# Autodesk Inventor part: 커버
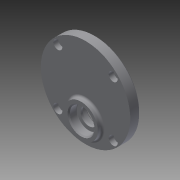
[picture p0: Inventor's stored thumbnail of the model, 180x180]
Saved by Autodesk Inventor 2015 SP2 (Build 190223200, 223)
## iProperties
Created: 2015-06
Part Number: 커버
Material: 일반
Document SubType Name: Modeling
Designer: AMC
Density: 1 g/cm^3
Appearance: 기본값
Author: AMC
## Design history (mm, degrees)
sketch "스케치1"
  geometry: C1 r 40 at (0, 0); 1 further point
  constraints: 1 centre point, 1 coincident
  dimensions: "d0" = 80 diameter of C1
extrude "돌출1" new body sketch "스케치1" distance "d1" = 9; taper "d2" = 0 deg
sketch "스케치2"
  geometry: C1 r 15 at (0, -20); 1 further point
  constraints: 1 centre point, 1 vertical alignment
  dimensions: "d3" = 30 diameter of C1; "d4" = 20 distance of point (0, 0) C1.centre
extrude "돌출2" join sketch "스케치2" distance "d5" = 4; taper "d6" = 0 deg
sketch "스케치3"
  geometry: C1 r 14 at (0, 20); C2 r 14 at (0, -11); 1 further point
  constraints: 2 centre point, 2 vertical alignment
  dimensions: "d7" = 28 diameter of C1; "d8" = 28 diameter of C2; "d9" = 11 distance of C2.centre point (0, 0); "d10" = 20 distance of point (0, 0) C1.centre
extrude "돌출3" join sketch "스케치3" distance "d11" = 3; taper "d12" = 0 deg
sketch "스케치4"
  geometry: C1 r 14 at (0, 0) reference; C2 r 14 at (0, -31) reference; C3 r 11 at (0, 0); 1 further point
  constraints: 1 centre point, 1 coincident
  dimensions: "d14" = 22 diameter of C3
extrude "돌출4" cut sketch "스케치4" distance "d15" = 7; taper "d16" = 0 deg
sketch "스케치5"
  geometry: C1 r 11 at (0, 0) reference; C2 r 40 at (0, -20) reference; C3 r 7.5 at (0, 0); 1 further point
  constraints: 1 centre point, 1 coincident
  dimensions: "d17" = 15 diameter of C3
extrude "돌출5" cut sketch "스케치5" distance "d18" = 2; taper "d19" = 0 deg
sketch "스케치6"
  geometry: C1 r 15 at (0, 0) reference; C2 r 11 at (0, 0); 1 further point
  constraints: 1 centre point, 1 coincident
  dimensions: "d20" = 22 diameter of C2
extrude "돌출6" cut sketch "스케치6" distance "d21" = 7; taper "d22" = 0 deg
sketch "스케치7"
  geometry: C1 r 11 at (0, 31) reference; C2 r 14 at (0, 31) reference; C3 r 14 at (0, 0) reference; C4 r 11 at (0, 0); 1 further point
  constraints: 1 centre point, 1 coincident
  dimensions: "d23" = 22 diameter of C4
extrude "돌출7" cut sketch "스케치7" distance "d24" = 7; taper "d25" = 0 deg
sketch "스케치8"
  geometry: C1 r 7.5 at (0, 31) reference; C2 r 11 at (0, 31) reference; C3 r 40 at (0, 11) reference; C4 r 9 at (0, 0); 2 further points
  constraints: 1 centre point, 1 coincident, 1 vertical alignment
  dimensions: "d26" = 18 diameter of C4
extrude "돌출8" cut sketch "스케치8" distance "d27" = 1; taper "d28" = 0 deg
sketch "스케치9"
  geometry: L1 (0, 0)-(24.749, 24.749); L2 (0, 0)-(35, 0); C1 r 11 at (0, -20) reference; C2 r 15 at (0, -20) reference; C3 r 40 at (0, 0) reference; 2 further points
  constraints: 4 end point, 1 coincident, 1 equal length, 1 horizontal
  dimensions: "d29" = 35 distance of L1.start L1.end; "d30" = 45 deg angle of L2 L1
hole "구멍1" sketch "스케치9" at (24.749, 24.749) diameter "d31" = 4.5; stored, may be unused: countersink angle "d35" = 90 deg, drill point angle "d37" = 118 deg; dims "d32" = 6, "d33" = 8, "d34" = 4.4, "d36" = 8
fillet "모깎기1" dims "d41" = 0.3
fillet "모깎기2" dims "d42" = 0.3
chamfer "모따기1" distance "d43" = 1; stored, may be unused: second distance "d44" = 2, angle "d45" = 45 deg
chamfer "모따기2" distance "d46" = 1; stored, may be unused: second distance "d47" = 2, angle "d48" = 45 deg
fillet "모깎기3" dims "d49" = 2
fillet "모깎기4" dims "d50" = 2
chamfer "모따기3" distance "d51" = 1; stored, may be unused: second distance "d52" = 2, angle "d53" = 45 deg
node "솔리드1"
pattern_circular "원형 패턴1" dims angle "d39" = 360 deg
node "절단 모서리 투영1"
node "절단 모서리 투영2"
node "절단 모서리 투영3"
node "절단 모서리 투영4"
node "절단 모서리 투영5"
node "절단 모서리 투영6"
